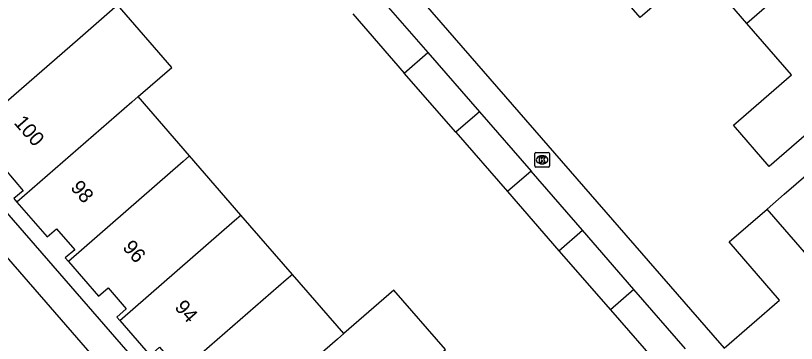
# Model space of a CAD drawing. Extents: x 155888 to 156864, y 383882 to 384671.
# Drawn here: x 156452 to 156505.7, y 384143.5 to 384166 of the extents above; entities that cross this region are included whole.
import ezdxf

# ---------------------------------------------------------------- set-up
doc = ezdxf.new("R2010")
doc.units = 0
for name, color, linetype in [('IMGEO_Kolk', 7, 'Continuous'), ('IMGEO_Pand', 7, 'Continuous'), ('IMGEO_Pand_nummerreeks', 7, 'Continuous'), ('IMGEO_Voetpad_open', 7, 'Continuous')]:
    doc.layers.add(name, color=color, linetype=linetype)

msp = doc.modelspace()

# ---------------------------------------------------------------- linework, layer by layer
at = {"layer": 'IMGEO_Kolk'}
for p, q in [((156487.751, 384155.672), (156487.751, 384156.524)), ((156487.826, 384156.598), (156488.678, 384156.598)), ((156488.239, 384156.378), (156488.264, 384156.378)), ((156488.752, 384156.524), (156488.752, 384155.672)), ((156488.262, 384155.818), (156488.237, 384155.818)), ((156488.678, 384155.598), (156487.826, 384155.598))]:
    msp.add_line(p, q, dxfattribs=at)
for points in [[(156487.751, 384155.672), (156487.751, 384156.524)], [(156487.826, 384156.598), (156488.678, 384156.598)], [(156488.072, 384156.298), (156488.195, 384156.298), (156488.195, 384156.147), (156488.325, 384156.298), (156488.489, 384156.298), (156488.343, 384156.147), (156488.496, 384155.898), (156488.344, 384155.898), (156488.259, 384156.062), (156488.195, 384155.995), (156488.195, 384155.898), (156488.072, 384155.898), (156488.072, 384156.298)], [(156488.752, 384156.524), (156488.752, 384155.672)], [(156488.678, 384155.598), (156487.826, 384155.598)]]:
    msp.add_lwpolyline(points, dxfattribs=at)
for centre, start, end in [((156487.828, 384156.522), 91.552, 178.448), ((156487.828, 384156.522), 91.552, 178.448), ((156488.676, 384156.522), 1.552, 88.448), ((156488.676, 384156.522), 1.552, 88.448), ((156487.828, 384155.674), 181.552, 268.448), ((156487.828, 384155.674), 181.552, 268.448), ((156488.676, 384155.674), 271.552, 358.448), ((156488.676, 384155.674), 271.552, 358.448)]:
    msp.add_arc(centre, 0.0765, start, end, dxfattribs=at)
for centre, major_axis, ratio, start_param, end_param in [((156488.238, 384156.098), (-0.387, 0.002), 0.722429, 4.712389, 7.853982), ((156488.263, 384156.098), (-0.39, 0.002), 0.717154, 1.570796, 4.712389)]:
    msp.add_ellipse(centre, major_axis=major_axis, ratio=ratio, start_param=start_param, end_param=end_param, dxfattribs=at)
at = {"layer": 'IMGEO_Pand'}
for points in [[(156502.344, 384165.487), (156500, 384168.196), (156498.993, 384169.36), (156494.99, 384165.895), (156492.538, 384168.728), (156500, 384175.186), (156503.816, 384178.488), (156503.718, 384178.601), (156503.96, 384178.81)], [(156508.717, 384171.037), (156502.344, 384165.487)], [(156476.853, 384167.547), (156480.397, 384163.475)], [(156448.379, 384157.493), (156456.294, 384164.363), (156459.05, 384166.755)], [(156460.461, 384160.441), (156462.782, 384162.455), (156459.05, 384166.755)], [(156475.232, 384166.136), (156478.775, 384162.064)], [(156515.523, 384165.52), (156515.265, 384165.303), (156515.167, 384165.416), (156503.874, 384155.644), (156501.423, 384158.476), (156505.419, 384161.934), (156502.344, 384165.487)], [(156478.775, 384162.064), (156480.397, 384163.475)], [(156480.397, 384163.475), (156483.94, 384159.402)], [(156482.319, 384157.991), (156478.775, 384162.064)], [(156460.461, 384160.441), (156460.026, 384160.063), (156452.122, 384153.187)], [(156464.003, 384156.361), (156460.461, 384160.441)], [(156483.94, 384159.402), (156482.319, 384157.991)], [(156483.94, 384159.402), (156487.491, 384155.321)], [(156482.319, 384157.991), (156485.869, 384153.911)], [(156448.379, 384157.493), (156450.661, 384154.854), (156451.311, 384155.417), (156452.565, 384153.969), (156451.919, 384153.421), (156452.122, 384153.187)], [(156464.003, 384156.361), (156463.568, 384155.982), (156455.666, 384149.103)], [(156467.537, 384152.29), (156464.003, 384156.361)], [(156487.491, 384155.321), (156485.869, 384153.911)], [(156491.032, 384151.252), (156487.491, 384155.321)], [(156503.731, 384152.702), (156504.905, 384153.721), (156506.566, 384155.163), (156510.041, 384151.16), (156513.63, 384154.276)], [(156485.869, 384153.911), (156489.41, 384149.841)], [(156452.122, 384153.187), (156454.203, 384150.787), (156454.853, 384151.35), (156456.109, 384149.894), (156455.454, 384149.347), (156455.666, 384149.103)], [(156500.779, 384143.137), (156504.594, 384146.446), (156501.128, 384150.443), (156503.731, 384152.702)], [(156513.744, 384141.181), (156503.731, 384152.702)], [(156459.196, 384145.034), (156467.101, 384151.91), (156467.537, 384152.29)], [(156471.08, 384148.209), (156467.537, 384152.29)], [(156489.41, 384149.841), (156491.032, 384151.252)], [(156494.576, 384147.178), (156491.032, 384151.252)], [(156489.41, 384149.841), (156492.954, 384145.767)], [(156455.666, 384149.103), (156457.744, 384146.715), (156458.393, 384147.28), (156459.648, 384145.829), (156458.988, 384145.273), (156459.196, 384145.034)], [(156471.08, 384148.209), (156470.643, 384147.829), (156462.744, 384140.954)], [(156474.621, 384144.13), (156471.08, 384148.209)], [(156478.23, 384140.116), (156481.599, 384143.047), (156478.058, 384147.119), (156474.621, 384144.13)], [(156494.576, 384147.178), (156492.954, 384145.767)], [(156498.127, 384143.096), (156494.576, 384147.178)], [(156492.954, 384145.767), (156496.505, 384141.686)], [(156459.196, 384145.034), (156461.292, 384142.633), (156461.94, 384143.198), (156463.199, 384141.759), (156462.534, 384141.194), (156462.744, 384140.954)], [(156474.621, 384144.13), (156474.184, 384143.75), (156466.286, 384136.882)]]:
    msp.add_lwpolyline(points, dxfattribs=at)
at = {"layer": 'IMGEO_Voetpad_open'}
for points in [[(156479.76, 384167.325), (156500, 384144.033), (156500.779, 384143.137)], [(156483.427, 384115.614), (156447.623, 384156.834)], [(156446.092, 384155.517), (156481.885, 384114.292)]]:
    msp.add_lwpolyline(points, dxfattribs=at)

# ---------------------------------------------------------------- texts
at = {"layer": 'IMGEO_Pand_nummerreeks'}
for s, p in [('100', (156451.877, 384158.617)), ('98', (156455.762, 384154.151)), ('96', (156459.342, 384150.035)), ('94', (156462.924, 384145.916))]:
    msp.add_text(s, height=1, rotation=311.0121, dxfattribs=at).set_placement(p)

doc.saveas('drawing.dxf')
